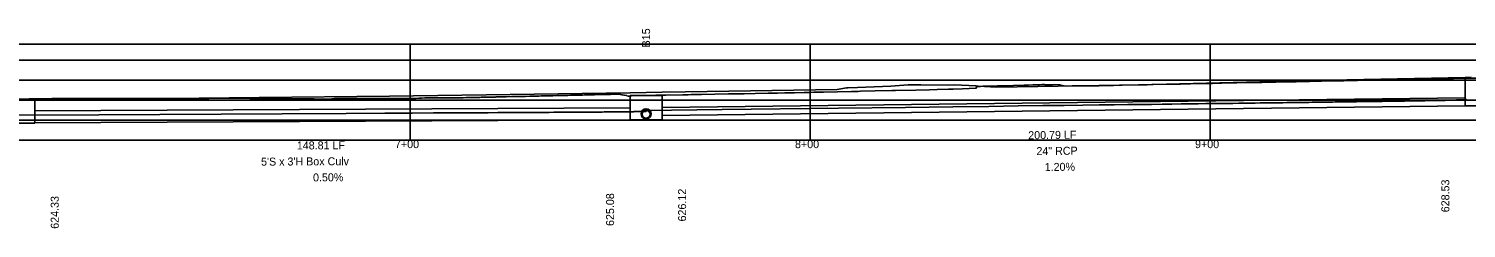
# Model space of a CAD drawing. Extents: x 2253035 to 2279930, y 13774972 to 13793443.
# Drawn here: x 2258990 to 2259349.4, y 13793382.2 to 13793432 of the extents above; entities that cross this region are included whole.
import ezdxf

# ---------------------------------------------------------------- set-up
doc = ezdxf.new("R2010")
doc.units = 0
for name, color, linetype in [('Default', 7, 'Continuous'), ('E_Utility_ATT_HH', 7, 'Continuous'), ('E_Utility_ATT_PR_PVC', 7, 'Continuous'), ('E_Utility_Electric_Overhead Electric Power Line_OE_Elevation', 7, 'Continuous'), ('E_Utility_Electric_Overhead Electric Power Line_OE_point', 7, 'Continuous'), ('E_Utillity_Water_Water Line_12in', 7, 'Continuous'), ('E_Utillity_Water_Water Line_1in', 7, 'Continuous'), ('E_Utillity_Water_Water Line_4in', 7, 'Continuous'), ('E_Utillity_Water_Water Line_8in', 7, 'Continuous')]:
    doc.layers.add(name, color=color, linetype=linetype)

msp = doc.modelspace()

# ---------------------------------------------------------------- linework, layer by layer
at = {"layer": 'Default'}
for p, q in [((2259085.4, 13793404.21), (2259085.4, 13793428.21)), ((2259185.4, 13793404.21), (2259185.4, 13793428.21)), ((2259285.4, 13793404.21), (2259285.4, 13793428.21))]:
    msp.add_line(p, q, dxfattribs=at)
at = {"layer": 'E_Utility_ATT_PR_PVC'}
msp.add_line((2259144.36, 13793411.73), (2259144.36, 13793411.62), dxfattribs=at)
for points in [[(2259144.36, 13793411.62), (2259163.34, 13793411.85), (2259192.44, 13793412.2), (2259209.23, 13793412.4), (2259221.01, 13793412.54), (2259230.05, 13793412.65), (2259237.39, 13793412.74), (2259243.55, 13793412.82), (2259248.86, 13793412.88), (2259253.51, 13793412.94), (2259257.65, 13793412.99), (2259261.38, 13793413.03), (2259264.76, 13793413.08), (2259267.86, 13793413.11), (2259270.72, 13793413.15), (2259273.36, 13793413.18), (2259275.82, 13793413.21), (2259278.13, 13793413.24), (2259280.29, 13793413.27), (2259282.33, 13793413.29), (2259284.25, 13793413.32), (2259286.07, 13793413.34), (2259287.8, 13793413.36), (2259289.44, 13793413.38), (2259291.01, 13793413.4), (2259292.51, 13793413.42), (2259293.94, 13793413.44), (2259295.31, 13793413.46), (2259296.63, 13793413.47), (2259297.89, 13793413.49), (2259299.1, 13793413.51), (2259300.28, 13793413.52), (2259301.4, 13793413.54), (2259302.49, 13793413.55), (2259303.54, 13793413.56), (2259304.56, 13793413.58), (2259305.54, 13793413.59), (2259306.49, 13793413.6), (2259307.42, 13793413.61), (2259308.31, 13793413.63), (2259309.18, 13793413.64), (2259310.02, 13793413.65), (2259310.84, 13793413.66), (2259311.63, 13793413.67), (2259312.4, 13793413.68), (2259313.16, 13793413.69), (2259313.89, 13793413.7), (2259314.6, 13793413.71), (2259315.3, 13793413.72), (2259315.97, 13793413.73), (2259316.63, 13793413.74), (2259317.28, 13793413.75), (2259317.91, 13793413.75), (2259318.52, 13793413.76), (2259319.12, 13793413.77), (2259319.7, 13793413.78), (2259320.28, 13793413.79), (2259320.83, 13793413.79), (2259321.38, 13793413.8), (2259321.92, 13793413.81), (2259322.44, 13793413.82), (2259322.95, 13793413.82), (2259323.45, 13793413.83), (2259323.94, 13793413.84), (2259324.42, 13793413.84), (2259324.89, 13793413.85), (2259325.35, 13793413.86), (2259325.8, 13793413.86), (2259326.25, 13793413.87), (2259326.68, 13793413.88), (2259327.11, 13793413.88), (2259327.52, 13793413.89), (2259327.93, 13793413.89), (2259328.33, 13793413.9), (2259328.73, 13793413.91), (2259329.11, 13793413.91), (2259329.49, 13793413.92), (2259329.86, 13793413.92), (2259330.23, 13793413.93), (2259330.59, 13793413.93), (2259330.94, 13793413.94), (2259331.29, 13793413.94), (2259331.63, 13793413.95), (2259331.96, 13793413.95), (2259332.29, 13793413.96), (2259332.61, 13793413.96), (2259332.93, 13793413.97), (2259333.24, 13793413.97), (2259333.54, 13793413.98), (2259333.85, 13793413.98), (2259334.14, 13793413.99), (2259334.43, 13793413.99), (2259334.72, 13793414), (2259335, 13793414), (2259335.27, 13793414), (2259335.55, 13793414.01), (2259335.81, 13793414.01), (2259336.08, 13793414.02), (2259336.34, 13793414.02), (2259336.59, 13793414.03), (2259336.84, 13793414.03), (2259337.09, 13793414.03), (2259337.33, 13793414.04), (2259337.57, 13793414.04), (2259337.8, 13793414.04), (2259338.03, 13793414.05), (2259338.26, 13793414.05), (2259338.48, 13793414.06), (2259338.7, 13793414.06), (2259338.92, 13793414.06), (2259339.13, 13793414.07), (2259339.34, 13793414.07), (2259339.55, 13793414.07), (2259339.76, 13793414.08), (2259339.96, 13793414.08), (2259340.15, 13793414.08), (2259340.35, 13793414.09), (2259340.54, 13793414.09), (2259340.73, 13793414.09), (2259340.91, 13793414.1), (2259341.1, 13793414.1), (2259341.28, 13793414.1), (2259341.45, 13793414.11), (2259341.63, 13793414.11), (2259341.8, 13793414.11), (2259341.97, 13793414.12), (2259342.13, 13793414.12), (2259342.3, 13793414.12), (2259342.46, 13793414.12), (2259342.62, 13793414.13), (2259342.78, 13793414.13), (2259342.93, 13793414.13), (2259343.08, 13793414.14), (2259343.23, 13793414.14), (2259343.38, 13793414.14), (2259343.52, 13793414.14), (2259343.67, 13793414.15), (2259343.81, 13793414.15), (2259343.95, 13793414.15), (2259344.08, 13793414.15), (2259344.22, 13793414.16), (2259344.35, 13793414.16), (2259344.48, 13793414.16), (2259344.61, 13793414.17), (2259344.73, 13793414.17), (2259344.86, 13793414.17), (2259344.98, 13793414.17), (2259345.1, 13793414.18), (2259345.22, 13793414.18), (2259345.34, 13793414.18), (2259345.45, 13793414.19), (2259345.57, 13793414.19), (2259345.68, 13793414.19), (2259345.79, 13793414.2), (2259345.9, 13793414.2), (2259346, 13793414.2), (2259346.11, 13793414.21), (2259346.21, 13793414.21), (2259346.31, 13793414.21), (2259346.41, 13793414.22), (2259346.51, 13793414.22), (2259346.61, 13793414.22), (2259346.7, 13793414.23), (2259346.8, 13793414.23), (2259346.89, 13793414.23), (2259346.98, 13793414.24), (2259347.07, 13793414.24), (2259347.16, 13793414.24), (2259347.24, 13793414.25), (2259347.33, 13793414.25), (2259347.41, 13793414.25), (2259347.49, 13793414.26), (2259347.57, 13793414.26), (2259347.65, 13793414.26), (2259347.73, 13793414.26), (2259347.81, 13793414.27), (2259347.88, 13793414.27), (2259347.96, 13793414.27), (2259348.03, 13793414.28), (2259348.1, 13793414.28), (2259348.17, 13793414.28), (2259348.24, 13793414.28), (2259348.31, 13793414.29), (2259348.37, 13793414.29), (2259348.44, 13793414.29), (2259348.5, 13793414.29), (2259348.57, 13793414.3), (2259348.63, 13793414.3), (2259348.69, 13793414.3), (2259348.75, 13793414.3), (2259348.81, 13793414.31), (2259348.86, 13793414.31), (2259348.92, 13793414.31), (2259348.98, 13793414.31), (2259349.03, 13793414.32), (2259349.08, 13793414.32), (2259349.13, 13793414.32), (2259349.19, 13793414.32), (2259349.23, 13793414.32), (2259349.28, 13793414.33), (2259349.33, 13793414.33), (2259349.38, 13793414.33), (2259349.42, 13793414.33)], [(2258987.54, 13793410.47), (2259007.59, 13793410.57), (2259053.38, 13793410.8), (2259069.4, 13793410.88), (2259079.04, 13793410.93), (2259085.9, 13793410.96), (2259091.19, 13793410.99), (2259095.49, 13793411.01), (2259099.1, 13793411.03), (2259102.2, 13793411.05), (2259104.91, 13793411.06), (2259107.31, 13793411.08), (2259109.46, 13793411.09), (2259111.41, 13793411.1), (2259113.18, 13793411.11), (2259114.8, 13793411.12), (2259116.3, 13793411.13), (2259117.68, 13793411.14), (2259118.97, 13793411.14), (2259120.17, 13793411.15), (2259121.3, 13793411.16), (2259122.35, 13793411.16), (2259123.34, 13793411.17), (2259124.28, 13793411.17), (2259125.16, 13793411.18), (2259126, 13793411.19), (2259126.79, 13793411.19), (2259127.54, 13793411.19), (2259128.26, 13793411.2), (2259128.94, 13793411.2), (2259129.59, 13793411.21), (2259130.2, 13793411.21), (2259130.8, 13793411.22), (2259131.36, 13793411.22), (2259131.9, 13793411.22), (2259132.42, 13793411.23), (2259132.92, 13793411.23), (2259133.39, 13793411.23), (2259133.85, 13793411.24), (2259134.29, 13793411.24), (2259134.71, 13793411.24), (2259135.11, 13793411.25), (2259135.5, 13793411.25), (2259135.87, 13793411.25), (2259136.23, 13793411.26), (2259136.58, 13793411.26), (2259136.91, 13793411.26), (2259137.23, 13793411.27), (2259137.54, 13793411.27), (2259137.84, 13793411.28), (2259138.13, 13793411.28), (2259138.4, 13793411.28), (2259138.67, 13793411.29), (2259138.92, 13793411.29), (2259139.17, 13793411.29), (2259139.41, 13793411.3), (2259139.64, 13793411.3), (2259139.86, 13793411.3), (2259140.07, 13793411.31), (2259140.28, 13793411.31), (2259140.48, 13793411.31), (2259140.67, 13793411.32), (2259140.85, 13793411.32), (2259141.03, 13793411.32), (2259141.2, 13793411.32), (2259141.37, 13793411.33), (2259141.52, 13793411.33), (2259141.68, 13793411.33), (2259141.82, 13793411.33), (2259141.96, 13793411.34), (2259142.1, 13793411.34), (2259142.23, 13793411.34), (2259142.36, 13793411.34), (2259142.48, 13793411.35), (2259142.59, 13793411.35), (2259142.7, 13793411.35), (2259142.81, 13793411.35), (2259142.91, 13793411.35), (2259143.01, 13793411.36), (2259143.1, 13793411.36), (2259143.19, 13793411.36), (2259143.28, 13793411.36), (2259143.36, 13793411.36), (2259143.43, 13793411.37), (2259143.51, 13793411.37), (2259143.58, 13793411.37), (2259143.64, 13793411.37), (2259143.71, 13793411.37), (2259143.77, 13793411.37), (2259143.82, 13793411.38), (2259143.88, 13793411.38), (2259143.93, 13793411.38), (2259143.97, 13793411.38), (2259144.02, 13793411.38), (2259144.06, 13793411.38), (2259144.1, 13793411.38), (2259144.13, 13793411.39), (2259144.16, 13793411.39), (2259144.19, 13793411.39), (2259144.22, 13793411.39), (2259144.24, 13793411.39), (2259144.27, 13793411.39), (2259144.29, 13793411.39), (2259144.3, 13793411.39), (2259144.32, 13793411.4), (2259144.33, 13793411.4), (2259144.34, 13793411.4), (2259144.35, 13793411.4), (2259144.35, 13793411.4), (2259144.36, 13793411.4), (2259144.36, 13793411.4), (2259144.36, 13793411.73)]]:
    msp.add_lwpolyline(points, dxfattribs=at)
at = {"layer": 'E_Utility_Electric_Overhead Electric Power Line_OE_Elevation'}
for p, q in [((2258385.4, 13793424.21), (2259679.58, 13793424.21)), ((2258385.4, 13793419.21), (2259679.58, 13793419.21)), ((2258385.4, 13793414.21), (2259679.58, 13793414.21)), ((2258385.4, 13793409.21), (2259679.58, 13793409.21))]:
    msp.add_line(p, q, dxfattribs=at)
at = {"layer": 'E_Utility_Electric_Overhead Electric Power Line_OE_point'}
msp.add_lwpolyline([(2258385.4, 13793404.21), (2258385.4, 13793428.21), (2259679.58, 13793428.21), (2259679.58, 13793404.21)], close=True, dxfattribs=at)
at = {"layer": 'E_Utillity_Water_Water Line_12in'}
for points in [[(2259349.15, 13793419.7), (2259352.15, 13793419.7), (2259352.15, 13793412.74), (2259349.15, 13793412.74)], [(2258983.54, 13793414.48), (2258991.54, 13793414.48), (2258991.54, 13793408.47), (2258983.54, 13793408.47)], [(2259140.36, 13793415.36), (2259148.36, 13793415.36), (2259148.36, 13793409.29), (2259140.36, 13793409.29)]]:
    msp.add_lwpolyline(points, close=True, dxfattribs=at)
at = {"layer": 'E_Utillity_Water_Water Line_1in'}
msp.add_lwpolyline([(2258987.54, 13793414.17), (2258991.54, 13793414.24), (2258991.54, 13793414.24), (2259004.17, 13793414.38), (2259010.21, 13793414.45), (2259047.61, 13793414.86), (2259080.23, 13793415.23), (2259110.36, 13793415.61), (2259110.4, 13793415.57), (2259140.36, 13793416), (2259140.36, 13793416), (2259144.36, 13793416.08), (2259144.36, 13793416.08), (2259148.36, 13793416.17), (2259148.36, 13793416.17), (2259154.21, 13793416.28), (2259192.11, 13793416.89), (2259194.49, 13793417.24), (2259194.55, 13793417.25), (2259194.83, 13793417.25), (2259197.21, 13793417.33), (2259205.53, 13793417.69), (2259209.9, 13793418), (2259213.03, 13793418), (2259219.81, 13793417.97), (2259221.43, 13793418.02), (2259226.82, 13793417.78), (2259227.02, 13793417.73), (2259227.02, 13793417.73), (2259227.27, 13793417.65), (2259227.28, 13793417.65), (2259227.36, 13793417.65), (2259232.08, 13793417.45), (2259267.75, 13793418.05), (2259311.1, 13793419.07), (2259349.15, 13793419.87), (2259349.15, 13793419.87), (2259350.65, 13793419.91)], dxfattribs=at)
at = {"layer": 'E_Utillity_Water_Water Line_4in'}
for p, q in [((2259148.36, 13793412.33), (2259349.15, 13793414.74)), ((2258991.54, 13793411.54), (2259140.36, 13793412.29)), ((2259148.36, 13793410.33), (2259349.15, 13793412.74)), ((2258991.54, 13793408.54), (2259140.36, 13793409.29))]:
    msp.add_line(p, q, dxfattribs=at)
for centre, radius in [((2259144.36, 13793410.78), 1.25), ((2259144.36, 13793410.66), 1)]:
    msp.add_circle(centre, radius, dxfattribs=at)
at = {"layer": 'E_Utillity_Water_Water Line_8in'}
msp.add_lwpolyline([(2258988.79, 13793414.48), (2258990.15, 13793414.51), (2258991.47, 13793414.51), (2258991.54, 13793414.51), (2258991.54, 13793414.51), (2258992.29, 13793414.53), (2258992.36, 13793414.53), (2258992.54, 13793414.53), (2258992.7, 13793414.53), (2258993.73, 13793414.53), (2258995.83, 13793414.61), (2258997.14, 13793414.61), (2258997.31, 13793414.61), (2258997.63, 13793414.61), (2258998.85, 13793414.61), (2259000.1, 13793414.61), (2259002.43, 13793414.61), (2259003.66, 13793414.63), (2259005.54, 13793414.63), (2259005.59, 13793414.63), (2259005.59, 13793414.63), (2259007.65, 13793414.63), (2259008.11, 13793414.63), (2259008.63, 13793414.63), (2259011.14, 13793414.63), (2259012.66, 13793414.63), (2259013.5, 13793414.63), (2259015.87, 13793414.63), (2259016.13, 13793414.63), (2259016.26, 13793414.63), (2259017.54, 13793414.63), (2259017.61, 13793414.63), (2259018.79, 13793414.63), (2259020.97, 13793414.63), (2259021.28, 13793414.63), (2259022.55, 13793414.63), (2259022.74, 13793414.63), (2259024.16, 13793414.63), (2259026.46, 13793414.63), (2259026.69, 13793414.63), (2259026.87, 13793414.63), (2259027.55, 13793414.63), (2259027.74, 13793414.63), (2259028.48, 13793414.63), (2259030.48, 13793414.63), (2259030.83, 13793414.64), (2259032.55, 13793414.63), (2259032.88, 13793414.63), (2259035.04, 13793414.63), (2259035.83, 13793414.67), (2259037.43, 13793414.66), (2259037.49, 13793414.66), (2259037.55, 13793414.66), (2259037.95, 13793414.71), (2259038.2, 13793414.7), (2259038.65, 13793414.7), (2259039.34, 13793414.69), (2259039.97, 13793414.69), (2259040.72, 13793414.68), (2259042.21, 13793414.66), (2259042.49, 13793414.66), (2259042.55, 13793414.66), (2259042.62, 13793414.66), (2259042.75, 13793414.66), (2259045.28, 13793414.63), (2259045.57, 13793414.63), (2259045.7, 13793414.63), (2259046.96, 13793414.62), (2259047.3, 13793414.61), (2259047.54, 13793414.61), (2259047.55, 13793414.61), (2259047.91, 13793414.61), (2259047.97, 13793414.61), (2259048.83, 13793414.6), (2259050.72, 13793414.58), (2259050.97, 13793414.58), (2259051.01, 13793414.58), (2259051.28, 13793414.58), (2259052.55, 13793414.56), (2259053.49, 13793414.56), (2259053.84, 13793414.55), (2259053.86, 13793414.55), (2259054.4, 13793414.55), (2259055.71, 13793414.54), (2259056.55, 13793414.53), (2259057.16, 13793414.52), (2259057.55, 13793414.52), (2259058, 13793414.52), (2259058.8, 13793414.51), (2259059.19, 13793414.51), (2259060.82, 13793414.49), (2259061.4, 13793414.49), (2259061.94, 13793414.48), (2259062.37, 13793414.48), (2259062.55, 13793414.48), (2259062.67, 13793414.48), (2259064.26, 13793414.47), (2259064.74, 13793414.46), (2259065.14, 13793414.46), (2259066.41, 13793414.57), (2259066.43, 13793414.57), (2259066.45, 13793414.57), (2259066.46, 13793414.57), (2259067.15, 13793414.57), (2259067.38, 13793414.58), (2259067.56, 13793414.58), (2259067.57, 13793414.58), (2259068.22, 13793414.58), (2259068.87, 13793414.58), (2259069.13, 13793414.59), (2259069.26, 13793414.59), (2259069.26, 13793414.59), (2259069.26, 13793414.59), (2259069.59, 13793414.59), (2259069.59, 13793414.59), (2259069.59, 13793414.59), (2259070.79, 13793414.59), (2259071.08, 13793414.6), (2259071.34, 13793414.6), (2259072.52, 13793414.6), (2259072.56, 13793414.6), (2259073.67, 13793414.6), (2259073.72, 13793414.6), (2259076.07, 13793414.6), (2259076.31, 13793414.6), (2259076.51, 13793414.6), (2259076.68, 13793414.6), (2259076.81, 13793414.6), (2259076.93, 13793414.6), (2259076.96, 13793414.6), (2259076.99, 13793414.6), (2259077.23, 13793414.6), (2259077.48, 13793414.6), (2259079.32, 13793414.6), (2259079.53, 13793414.61), (2259082.54, 13793414.61), (2259083.02, 13793414.61), (2259085.01, 13793414.61), (2259085.03, 13793414.61), (2259085.22, 13793414.61), (2259085.24, 13793414.61), (2259086.63, 13793414.61), (2259086.77, 13793414.61), (2259087.54, 13793414.73), (2259087.62, 13793414.73), (2259087.64, 13793414.73), (2259088.32, 13793414.73), (2259089.08, 13793414.8), (2259090.21, 13793414.8), (2259091.74, 13793414.8), (2259092.53, 13793414.8), (2259092.56, 13793414.8), (2259094.13, 13793414.8), (2259095.49, 13793414.81), (2259095.59, 13793414.81), (2259097.56, 13793414.81), (2259098.67, 13793414.81), (2259099.35, 13793414.83), (2259099.46, 13793414.83), (2259101.77, 13793414.88), (2259102.25, 13793414.89), (2259102.56, 13793414.89), (2259102.8, 13793414.9), (2259103.15, 13793414.91), (2259103.97, 13793414.93), (2259105.14, 13793414.95), (2259106.64, 13793414.98), (2259106.92, 13793415.01), (2259107.4, 13793415.01), (2259107.56, 13793415.01), (2259107.56, 13793415.01), (2259107.99, 13793415.01), (2259108.39, 13793415.02), (2259108.45, 13793415.02), (2259109.4, 13793415.04), (2259110.68, 13793415.07), (2259111.24, 13793415.08), (2259111.53, 13793415.09), (2259112.37, 13793415.11), (2259112.57, 13793415.11), (2259113.4, 13793415.13), (2259114.22, 13793415.15), (2259115.34, 13793415.18), (2259116.8, 13793415.21), (2259116.83, 13793415.21), (2259116.91, 13793415.21), (2259117.47, 13793415.23), (2259117.57, 13793415.23), (2259118.17, 13793415.24), (2259118.29, 13793415.24), (2259118.3, 13793415.24), (2259118.71, 13793415.25), (2259119.75, 13793415.28), (2259120.55, 13793415.3), (2259121.09, 13793415.31), (2259122.25, 13793415.34), (2259122.57, 13793415.34), (2259122.57, 13793415.34), (2259122.57, 13793415.34), (2259124.4, 13793415.39), (2259124.64, 13793415.39), (2259124.8, 13793415.4), (2259125.49, 13793415.41), (2259125.56, 13793415.41), (2259125.58, 13793415.41), (2259126.51, 13793415.44), (2259127.1, 13793415.45), (2259127.39, 13793415.46), (2259127.57, 13793415.46), (2259128.45, 13793415.48), (2259128.98, 13793415.5), (2259130.1, 13793415.52), (2259130.8, 13793415.54), (2259131.27, 13793415.55), (2259131.47, 13793415.56), (2259132.57, 13793415.58), (2259132.65, 13793415.59), (2259133.27, 13793415.6), (2259133.76, 13793415.61), (2259135.24, 13793415.62), (2259135.46, 13793415.65), (2259136.3, 13793415.68), (2259136.72, 13793415.69), (2259137.11, 13793415.7), (2259137.33, 13793415.7), (2259137.47, 13793415.7), (2259137.57, 13793415.71), (2259137.61, 13793415.7), (2259137.68, 13793415.68), (2259138, 13793415.61), (2259138.29, 13793415.55), (2259138.49, 13793415.51), (2259138.84, 13793415.43), (2259138.93, 13793415.41), (2259139.47, 13793415.36), (2259139.57, 13793415.27), (2259139.85, 13793415.21), (2259140.36, 13793415.23), (2259140.36, 13793415.23), (2259140.6, 13793415.24), (2259144.01, 13793415.34), (2259144.04, 13793415.35), (2259144.21, 13793415.36), (2259144.36, 13793415.36), (2259144.36, 13793415.36), (2259145.82, 13793415.4), (2259145.92, 13793415.39), (2259146.78, 13793415.41), (2259147.89, 13793415.43), (2259148.36, 13793415.44), (2259148.36, 13793415.44), (2259149.29, 13793415.46), (2259153.54, 13793415.53), (2259154.84, 13793415.55), (2259155.65, 13793415.57), (2259157.06, 13793415.59), (2259157.41, 13793415.6), (2259158.19, 13793415.61), (2259161.58, 13793415.67), (2259164.93, 13793415.74), (2259166.01, 13793415.76), (2259166.35, 13793415.76), (2259167.21, 13793415.78), (2259168.91, 13793415.81), (2259171.66, 13793415.87), (2259174.87, 13793415.93), (2259176.11, 13793415.95), (2259177.19, 13793415.97), (2259179.06, 13793416.01), (2259181.45, 13793416.06), (2259183.88, 13793416.11), (2259185.18, 13793416.14), (2259186.31, 13793416.16), (2259188.58, 13793416.21), (2259188.64, 13793416.21), (2259188.71, 13793416.21), (2259195.72, 13793416.36), (2259196.11, 13793416.37), (2259197.18, 13793416.4), (2259197.31, 13793416.4), (2259197.38, 13793416.4), (2259197.92, 13793416.41), (2259201.63, 13793416.5), (2259205.77, 13793416.59), (2259206.09, 13793416.6), (2259206.75, 13793416.61), (2259211.82, 13793416.73), (2259215.25, 13793416.81), (2259217.14, 13793416.86), (2259219.93, 13793416.93), (2259220.81, 13793416.95), (2259221.16, 13793416.96), (2259223.46, 13793417.01), (2259226.79, 13793417.19), (2259226.88, 13793417.2), (2259226.9, 13793417.22), (2259226.98, 13793417.46), (2259226.99, 13793417.51), (2259227, 13793417.53), (2259227.03, 13793417.61), (2259227.95, 13793417.64), (2259228.55, 13793417.66), (2259232.19, 13793417.77), (2259233.19, 13793417.8), (2259233.41, 13793417.8), (2259233.42, 13793417.8), (2259233.42, 13793417.8), (2259233.42, 13793417.8), (2259233.48, 13793417.8), (2259233.55, 13793417.8), (2259233.57, 13793417.8), (2259233.79, 13793417.81), (2259236.23, 13793417.88), (2259238.85, 13793417.95), (2259239.08, 13793417.95), (2259239.56, 13793417.95), (2259239.57, 13793417.95), (2259239.62, 13793417.95), (2259239.92, 13793417.94), (2259241.01, 13793418.01), (2259242.69, 13793418.05), (2259243.4, 13793418.07), (2259243.92, 13793418.07), (2259244.04, 13793418.06), (2259244.76, 13793418.06), (2259245.47, 13793418.05), (2259245.99, 13793418.04), (2259246.48, 13793418.07), (2259247.61, 13793418.02), (2259247.63, 13793418.02), (2259247.81, 13793418.01), (2259247.92, 13793417.98), (2259248.01, 13793417.95), (2259248.45, 13793417.82), (2259248.47, 13793417.81), (2259248.48, 13793417.81), (2259248.5, 13793417.81), (2259248.85, 13793417.77), (2259248.87, 13793417.78), (2259249.56, 13793417.71), (2259250.9, 13793417.78), (2259251.53, 13793417.78), (2259252.58, 13793417.76), (2259254.2, 13793417.74), (2259256.36, 13793417.79), (2259256.45, 13793417.79), (2259257.54, 13793417.81), (2259257.6, 13793417.81), (2259257.7, 13793417.82), (2259257.7, 13793417.82), (2259257.7, 13793417.82), (2259257.7, 13793417.82), (2259258.55, 13793417.85), (2259258.58, 13793417.85), (2259258.6, 13793417.85), (2259258.82, 13793417.85), (2259258.84, 13793417.85), (2259258.94, 13793417.85), (2259258.94, 13793417.85), (2259258.98, 13793417.85), (2259259.09, 13793417.85), (2259259.32, 13793417.85), (2259259.43, 13793417.85), (2259259.44, 13793417.85), (2259260.36, 13793417.87), (2259260.94, 13793417.88), (2259261.18, 13793417.88), (2259263.05, 13793417.92), (2259263.4, 13793417.93), (2259267.48, 13793418.01), (2259267.62, 13793418.02), (2259267.63, 13793418.02), (2259267.64, 13793418.02), (2259267.67, 13793418.02), (2259267.76, 13793418.02), (2259267.76, 13793418.02), (2259267.76, 13793418.02), (2259268.16, 13793418.03), (2259268.2, 13793418.03), (2259269.59, 13793418.06), (2259270.8, 13793418.08), (2259275.36, 13793418.17), (2259276.38, 13793418.19), (2259276.39, 13793418.19), (2259276.44, 13793418.19), (2259276.7, 13793418.2), (2259277.32, 13793418.21), (2259277.92, 13793418.22), (2259280.46, 13793418.28), (2259285.27, 13793418.37), (2259285.65, 13793418.38), (2259285.94, 13793418.39), (2259286.3, 13793418.4), (2259287.16, 13793418.41), (2259288.02, 13793418.43), (2259288.08, 13793418.43), (2259288.18, 13793418.43), (2259292.06, 13793418.51), (2259297.01, 13793418.61), (2259297.62, 13793418.63), (2259297.77, 13793418.63), (2259298.16, 13793418.64), (2259298.25, 13793418.64), (2259301.8, 13793418.71), (2259306.33, 13793418.8), (2259306.47, 13793418.8), (2259306.85, 13793418.81), (2259308.41, 13793418.84), (2259310.18, 13793418.88), (2259316.32, 13793419.01), (2259316.55, 13793419.01), (2259316.69, 13793419.01), (2259318.43, 13793419.05), (2259318.58, 13793419.05), (2259318.81, 13793419.06), (2259322.21, 13793419.12), (2259326.53, 13793419.21), (2259327.62, 13793419.24), (2259327.82, 13793419.24), (2259328.56, 13793419.25), (2259328.74, 13793419.26), (2259331.86, 13793419.32), (2259336.37, 13793419.41), (2259336.6, 13793419.42), (2259336.64, 13793419.42), (2259336.9, 13793419.42), (2259338.9, 13793419.46), (2259339.25, 13793419.47), (2259340.96, 13793419.51), (2259346.21, 13793419.61), (2259347.62, 13793419.65), (2259347.83, 13793419.65), (2259348.82, 13793419.67), (2259349.07, 13793419.67), (2259349.15, 13793419.67), (2259349.15, 13793419.67), (2259349.48, 13793419.68)], dxfattribs=at)

# ---------------------------------------------------------------- texts
at = {"layer": 'Default'}
for s, p in [('7+00', (2259081.59, 13793402.21)), ('8+00', (2259181.59, 13793402.21)), ('9+00', (2259281.59, 13793402.21))]:
    msp.add_text(s, height=2, dxfattribs=at).set_placement(p)
at = {"layer": 'E_Utility_ATT_HH'}
for s, rotation, p in [('B15', 90, (2259145.36, 13793427.38)), ('200.79 LF', 0.6875, (2259239.9, 13793404.43)), ('148.81 LF', 0.2865, (2259057.06, 13793401.87)), ('24" RCP', 0.6875, (2259241.95, 13793400.46)), ("5'S x 3'H Box Culv", 0.2865, (2259048.12, 13793397.83)), ('0.50%', 0.2865, (2259061.11, 13793393.89)), ('1.20%', 0.6875, (2259244.01, 13793396.48)), ('626.12', 90, (2259154.36, 13793383.89)), ('628.53', 90, (2259345.15, 13793386.18)), ('624.33', 90, (2258997.54, 13793382.06)), ('625.08', 90, (2259136.36, 13793382.76))]:
    msp.add_text(s, height=2, rotation=rotation, dxfattribs=at).set_placement(p)

doc.saveas('drawing.dxf')
